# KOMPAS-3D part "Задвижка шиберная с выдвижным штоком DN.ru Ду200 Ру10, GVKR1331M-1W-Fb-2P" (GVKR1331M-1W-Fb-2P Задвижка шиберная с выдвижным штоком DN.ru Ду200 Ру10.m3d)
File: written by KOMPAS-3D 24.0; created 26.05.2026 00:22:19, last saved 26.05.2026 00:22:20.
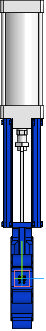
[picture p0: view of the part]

Document properties: Автор: R2D2; Полное имя файла: E:\Работа\Зайцев\GVKR1331M-1W-Fb-2P Задвижка шиберная с выдвижным штоком DN.ru Ду50-300 Ру16-10-6 с пневмоприводом\исходные материалы\DN200\DN200\GVKR1331M-1W-Fb-2P Задвижка шиберная с выдвижным штоком DN.ru Ду200 Ру10.m3d

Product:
- Part/product: Задвижка шиберная с выдвижным штоком DN.ru Ду200 Ру10  | designation GVKR1331M-1W-Fb-2P
    Масса: 31
    Раздел спецификации: Прочие изделия
    Примечание: D040-08797

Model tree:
1. Операция без истории:1

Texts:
  GVKR1331M-1W-Fb-2P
